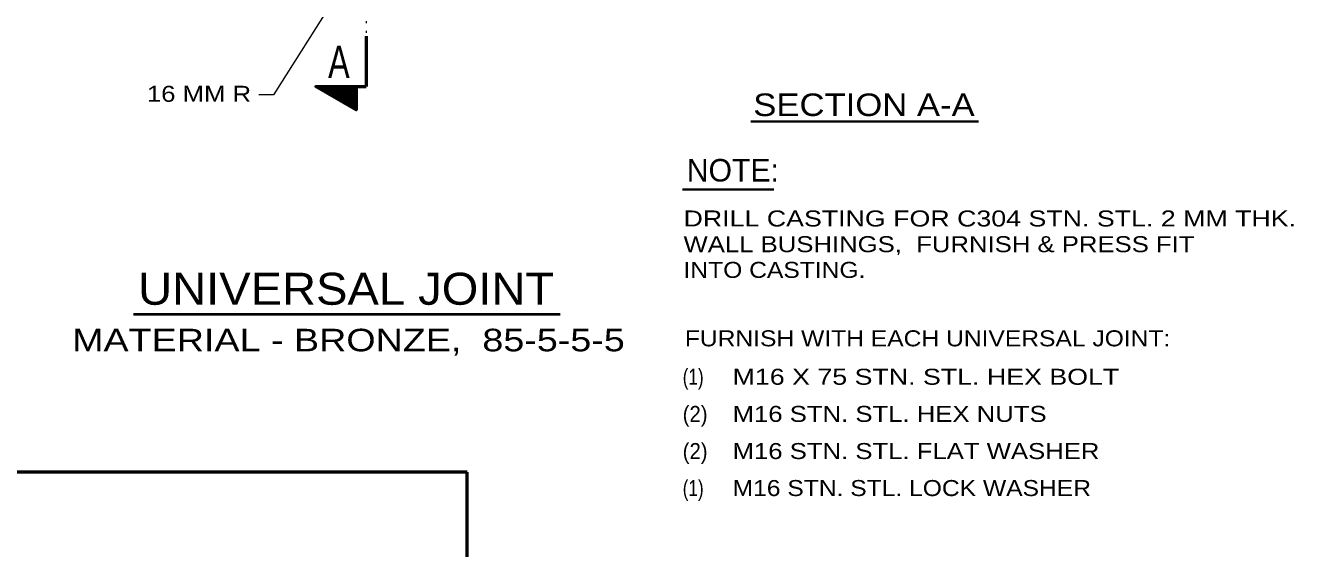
# Model space of a CAD drawing. Extents: x 312583 to 312854, y 144419 to 144597.
# Drawn here: x 312663.9 to 312724.1, y 144532 to 144556.8 of the extents above; entities that cross this region are included whole.
import ezdxf
from ezdxf.enums import TextEntityAlignment as Align

# ---------------------------------------------------------------- set-up
doc = ezdxf.new("R2010")
doc.units = 0
doc.header["$LTSCALE"] = 0.3
doc.linetypes.add('DOTTED', pattern=[1.5, 0.3, -1.2])
doc.layers.add('1', color=7, linetype='Continuous', lineweight=40)
doc.layers.add('2', color=7, linetype='Continuous', lineweight=13)

msp = doc.modelspace()

# ---------------------------------------------------------------- linework, layer by layer
at = {"layer": '1', "lineweight": 53}
for p, q in [((312680.079, 144556.2916), (312680.079, 144553.8996)), ((312679.6036, 144553.8996), (312680.079, 144553.8996)), ((312684.879, 144535.5916), (312616.5, 144535.5916)), ((312684.879, 144498.2549), (312684.879, 144535.5916))]:
    msp.add_line(p, q, dxfattribs=at)
at = {"layer": '1', "lineweight": 35}
for p, q in [((312677.7023, 144553.8996), (312677.7023, 144553.8842)), ((312677.733, 144553.8996), (312677.7253, 144553.8766)), ((312677.7636, 144553.8996), (312677.7406, 144553.8612)), ((312677.7866, 144553.8996), (312677.7636, 144553.8536)), ((312677.8173, 144553.8996), (312677.7866, 144553.8382)), ((312677.8403, 144553.8996), (312677.802, 144553.8306)), ((312677.871, 144553.8996), (312677.825, 144553.8152)), ((312677.9016, 144553.8996), (312677.848, 144553.8076)), ((312677.9323, 144553.8996), (312677.8633, 144553.7922)), ((312677.9553, 144553.8996), (312677.8863, 144553.7846)), ((312677.9783, 144553.8996), (312677.9093, 144553.7692)), ((312678.009, 144553.8996), (312677.9323, 144553.7616)), ((312678.032, 144553.8996), (312677.9476, 144553.7462)), ((312678.0626, 144553.8996), (312677.9706, 144553.7309)), ((312678.0933, 144553.8996), (312677.9936, 144553.7232)), ((312678.124, 144553.8996), (312678.009, 144553.7079)), ((312678.147, 144553.8996), (312678.032, 144553.6926)), ((312678.1776, 144553.8996), (312678.055, 144553.6849)), ((312678.2006, 144553.8996), (312678.0703, 144553.6696)), ((312678.2313, 144553.8996), (312678.0933, 144553.6619)), ((312678.262, 144553.8996), (312678.1163, 144553.6466)), ((312678.285, 144553.8996), (312678.1316, 144553.6389)), ((312678.3156, 144553.8996), (312678.1623, 144553.6236)), ((312678.3386, 144553.8996), (312678.1776, 144553.6159)), ((312678.3693, 144553.8996), (312678.2006, 144553.6006)), ((312678.4, 144553.8996), (312678.2236, 144553.5929)), ((312678.423, 144553.8996), (312678.239, 144553.5776)), ((312678.4536, 144553.8996), (312678.262, 144553.5699)), ((312678.4766, 144553.8996), (312678.285, 144553.5546)), ((312678.5073, 144553.8996), (312678.3003, 144553.5392)), ((312678.5303, 144553.8996), (312678.3233, 144553.5316)), ((312678.561, 144553.8996), (312678.3463, 144553.5162)), ((312678.5916, 144553.8996), (312678.3616, 144553.5009)), ((312678.6223, 144553.8996), (312678.3846, 144553.4932)), ((312678.6453, 144553.8996), (312678.4076, 144553.4779)), ((312678.6683, 144553.8996), (312678.4306, 144553.4702)), ((312678.699, 144553.8996), (312678.446, 144553.4549)), ((312678.7296, 144553.8996), (312678.469, 144553.4472)), ((312678.7526, 144553.8996), (312678.492, 144553.4319)), ((312678.7833, 144553.8996), (312678.5073, 144553.4242)), ((312678.814, 144553.8996), (312678.5303, 144553.4089)), ((312678.837, 144553.8996), (312678.5533, 144553.4012)), ((312678.8676, 144553.8996), (312678.5686, 144553.3859)), ((312678.8983, 144553.8996), (312678.5916, 144553.3782)), ((312678.9213, 144553.8996), (312678.6146, 144553.3629)), ((312678.952, 144553.8919), (312678.63, 144553.3476)), ((312678.975, 144553.8996), (312678.6606, 144553.3399)), ((312679.0056, 144553.8996), (312678.676, 144553.3246)), ((312679.0286, 144553.8996), (312678.699, 144553.3169)), ((312679.0593, 144553.8996), (312678.722, 144553.3016)), ((312679.09, 144553.8996), (312678.7373, 144553.2939)), ((312679.1206, 144553.8996), (312678.7603, 144553.2786)), ((312679.1436, 144553.8996), (312678.7833, 144553.2709)), ((312679.1666, 144553.8996), (312678.7986, 144553.2556)), ((312679.1973, 144553.8919), (312678.8216, 144553.2479)), ((312679.228, 144553.8996), (312678.8446, 144553.2326)), ((312679.251, 144553.8996), (312678.86, 144553.2249)), ((312679.2816, 144553.8996), (312678.883, 144553.2096)), ((312679.3123, 144553.8996), (312678.906, 144553.1942)), ((312679.3353, 144553.8996), (312678.929, 144553.1866)), ((312679.366, 144553.8996), (312678.9443, 144553.1712)), ((312679.3966, 144553.8996), (312678.9673, 144553.1559)), ((312679.4196, 144553.8919), (312678.9903, 144553.1482)), ((312679.4503, 144553.8919), (312679.0056, 144553.1329)), ((312679.4733, 144553.8996), (312679.0286, 144553.1252)), ((312679.504, 144553.8996), (312679.0516, 144553.1099)), ((312679.527, 144553.8996), (312679.067, 144553.1022)), ((312679.5576, 144553.8996), (312679.09, 144553.0869)), ((312679.5883, 144553.8996), (312679.113, 144553.0792)), ((312679.6036, 144553.8766), (312679.1283, 144553.0639)), ((312679.6036, 144553.8229), (312679.159, 144553.0562)), ((312679.6036, 144553.7846), (312679.1743, 144553.0409)), ((312679.6036, 144553.7309), (312679.1973, 144553.0332)), ((312679.6036, 144553.6849), (312679.2203, 144553.0179)), ((312679.6036, 144553.6389), (312679.2356, 144553.0026)), ((312679.6036, 144553.5929), (312679.2586, 144552.9949)), ((312679.6036, 144553.5392), (312679.2816, 144552.9796)), ((312679.6036, 144553.4932), (312679.297, 144552.9642)), ((312679.6036, 144553.4472), (312679.32, 144552.9566)), ((312679.6036, 144553.3936), (312679.3353, 144552.9412)), ((312679.6036, 144553.3476), (312679.3583, 144552.9336)), ((312679.6036, 144553.3016), (312679.3813, 144552.9182)), ((312679.6036, 144553.2479), (312679.3966, 144552.9106)), ((312679.6036, 144553.2019), (312679.4273, 144552.8952)), ((312679.6036, 144553.1559), (312679.4426, 144552.8876)), ((312679.6036, 144553.1099), (312679.4656, 144552.8722)), ((312679.6036, 144553.0562), (312679.4886, 144552.8646)), ((312679.6036, 144553.0179), (312679.504, 144552.8492)), ((312679.6036, 144552.9642), (312679.527, 144552.8416)), ((312679.6036, 144552.9182), (312679.55, 144552.8262)), ((312679.6036, 144552.8646), (312679.5653, 144552.8109)), ((312679.6036, 144552.8186), (312679.5883, 144552.8032))]:
    msp.add_line(p, q, dxfattribs=at)
at = {"layer": '1', "lineweight": 53}
msp.add_lwpolyline([(312679.6036, 144553.8996), (312679.6036, 144552.7879), (312677.687, 144553.8996)], close=True, dxfattribs=at)
at = {"layer": '2'}
for p, q in [((312680.079, 144560.4469), (312675.6783, 144553.4932)), ((312675.6783, 144553.4932), (312674.9883, 144553.4932))]:
    msp.add_line(p, q, dxfattribs=at)
at = {"layer": '2', "linetype": 'DOTTED'}
msp.add_line((312680.079, 144559.2969), (312680.079, 144556.2916), dxfattribs=at)
at = {"layer": '2', "lineweight": 35}
for p, q in [((312698.3503, 144552.2359), (312709.1576, 144552.2359)), ((312695.0968, 144549.0082), (312699.4361, 144549.0082))]:
    msp.add_line(p, q, dxfattribs=at)
at = {"layer": '2', "lineweight": 40}
msp.add_line((312669.0311, 144543.0896), (312689.2992, 144543.0896), dxfattribs=at)

# ---------------------------------------------------------------- texts
at = {"layer": '1', "width": 0.75}
msp.add_text('A', height=1.533, dxfattribs=at).set_placement((312678.7871, 144554.2982), align=Align.CENTER)
at = {"layer": '2'}
for s, width, p in [('16 MM R', 1.2, (312669.6729, 144553.1683)), ('DRILL CASTING FOR C304 STN. STL. 2 MM THK.', 1.25, (312695.1504, 144547.2516)), ('WALL BUSHINGS,  FURNISH & PRESS FIT', 1.2, (312695.1504, 144546.0316)), ('INTO CASTING.', 1.15, (312695.1504, 144544.8116)), ('FURNISH WITH EACH UNIVERSAL JOINT:', 1.15, (312695.2118, 144541.5629)), ('(1)', 0.8, (312695.1121, 144539.7382)), ('M16 X 75 STN. STL. HEX BOLT', 1.25, (312697.4811, 144539.7382)), ('(2)', 0.95, (312695.1121, 144537.9749)), ('M16 STN. STL. HEX NUTS', 1.2, (312697.4811, 144537.9749)), ('(2)', 0.95, (312695.1121, 144536.2116)), ('M16 STN. STL. FLAT WASHER', 1.2, (312697.4811, 144536.2116)), ('(1)', 0.8, (312695.1121, 144534.4559)), ('M16 STN. STL. LOCK WASHER', 1.15, (312697.4811, 144534.4559))]:
    msp.add_text(s, height=0.76, dxfattribs=dict(at, width=width)).set_placement(p)
for s, height, width, p in [('SECTION A-A', 1.07, 1.15, (312703.718, 144552.4943)), ('UNIVERSAL JOINT', 1.52, 1.1, (312679.1328, 144543.5363)), ('MATERIAL - BRONZE,  85-5-5-5', 1.07, 1.25, (312679.2414, 144541.3258))]:
    msp.add_text(s, height=height, dxfattribs=dict(at, width=width)).set_placement(p, align=Align.CENTER)
msp.add_text('NOTE:', height=1.07, dxfattribs=at).set_placement((312697.492, 144549.3863), align=Align.CENTER)

doc.saveas('drawing.dxf')
